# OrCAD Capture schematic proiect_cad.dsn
size Custom
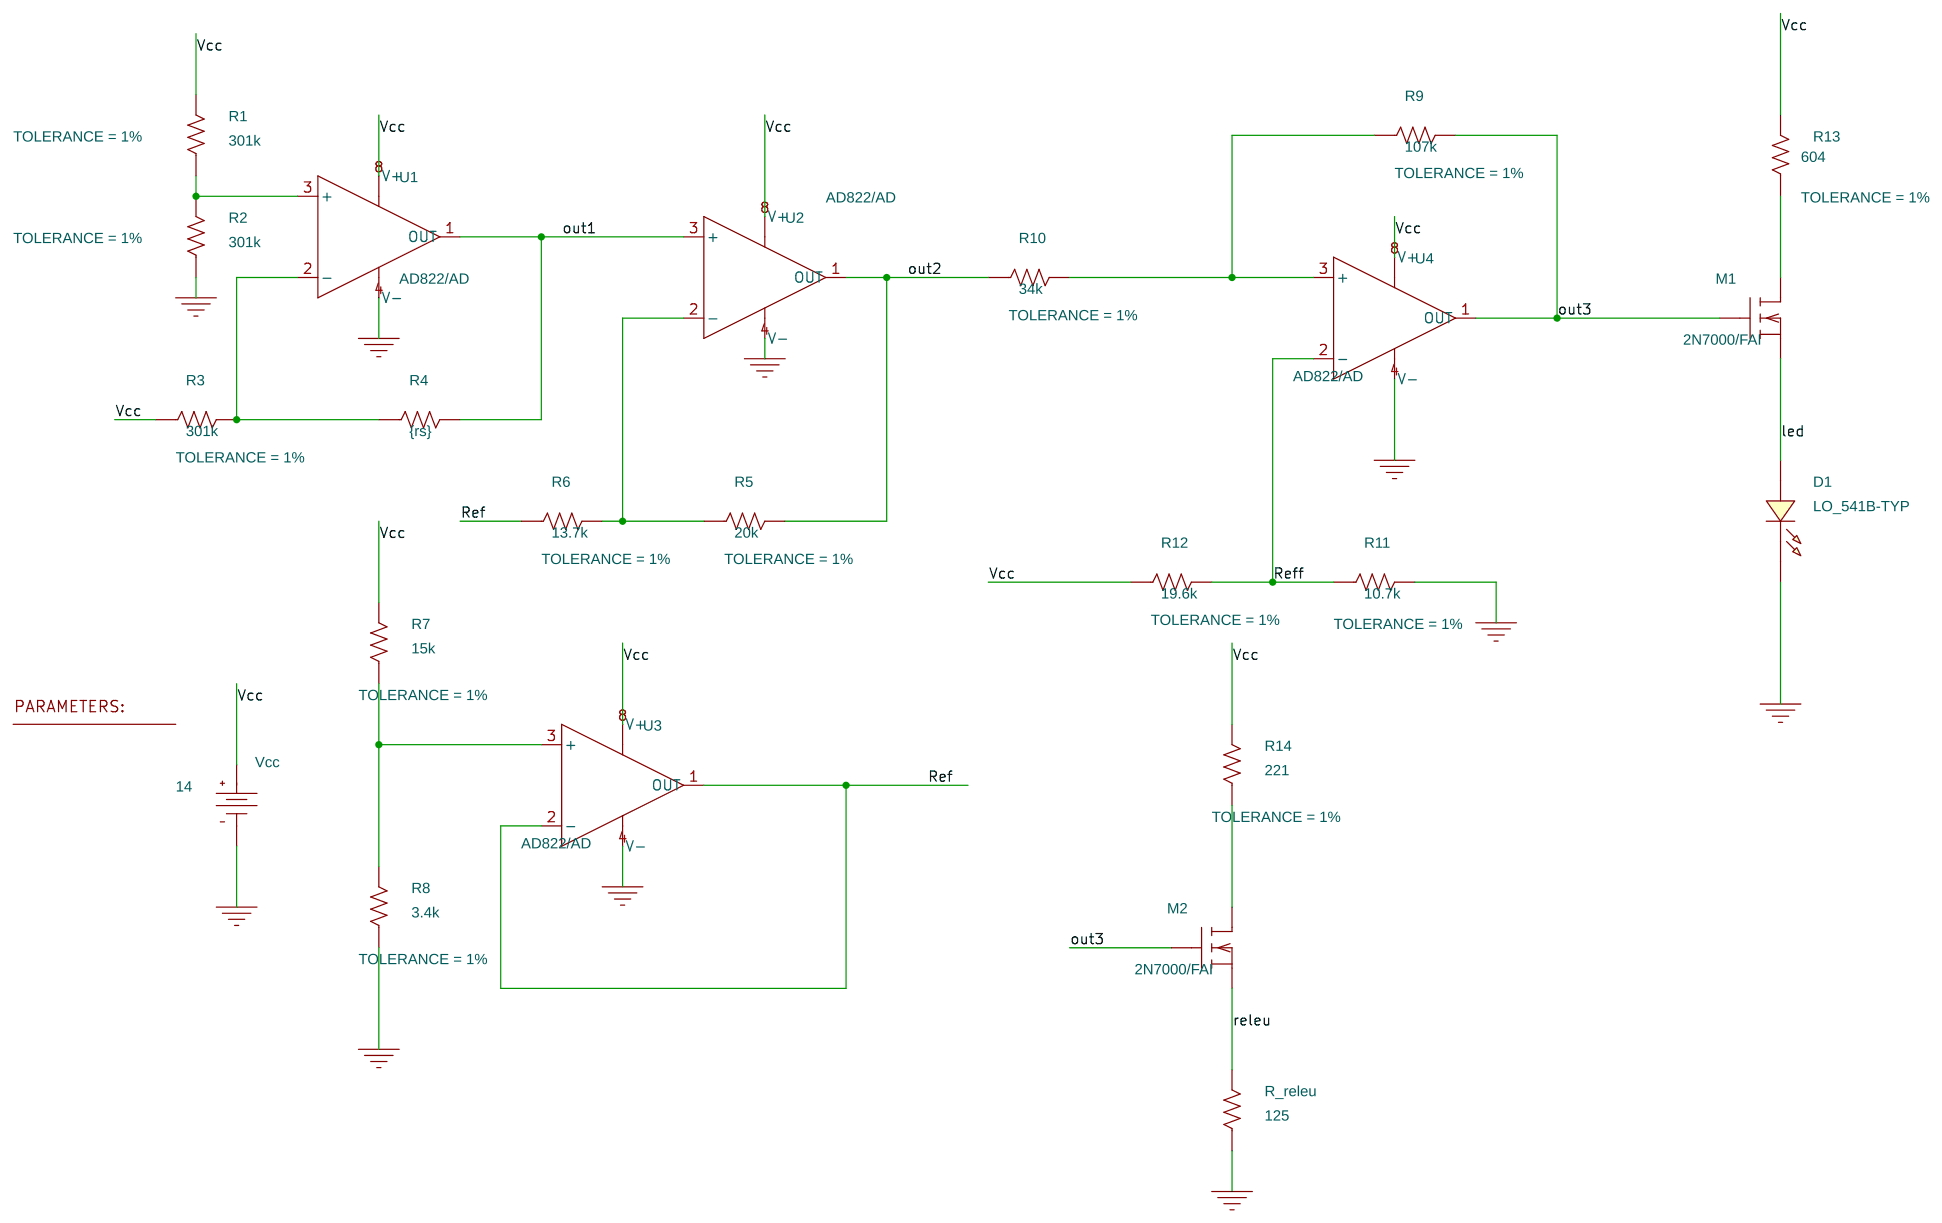
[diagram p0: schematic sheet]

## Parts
1  PARAM
D1  LO_541B-TYP
M1  2N7000/FAI  [TO92]
M2  2N7000/FAI  [TO92]
R1  301k  [AXRC05]
R2  301k  [AXRC05]
R3  301k  [AXRC05]
R4  {rs}  [AXRC05]
R5  20k  [AXRC05]
R6  13.7k  [AXRC05]
R7  15k  [AXRC05]
R8  3.4k  [AXRC05]
R9  107k  [AXRC05]
R10  34k  [AXRC05]
R11  10.7k  [AXRC05]
R12  19.6k  [AXRC05]
R13  604  [AXRC05]
R14  221  [AXRC05]
R_releu  125  [AXRC05]
U1  AD822/AD  [DIP1008W300L450]
U2  AD822/AD  [DIP1008W300L450]
U3  AD822/AD  [DIP1008W300L450]
U4  AD822/AD  [DIP1008W300L450]
Vcc  VDC

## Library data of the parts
1 = PARAM: releu: 1k; rled: 1k; rs: 100k
D1 = LO_541B-TYP
M1 M2 = 2N7000_FAI
R1-R3 R5-R14 = R: TOLERANCE: 1%
R4 R_releu = R
U1-U4 = AD822_AD
Vcc = VDC: DC: 14

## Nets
Vcc: R1.2 R3.1 R7.2 R12.1 R13.2 R14.2 U1.8(V+) U2.8(V+) U3.8(V+) U4.8(V+) Vcc.0(+)
0: D1.2 R2.1 R8.1 R11.2 R_releu.1 U1.4(V-) U2.4(V-) U3.4(V-) U4.4(V-) Vcc.1(-)
led: D1.1 M1.0(s)
out1: R4.2 U1.1(OUT) U2.3(+)
out2: R5.2 R10.1 U2.1(OUT)
out3: M1.1(g) M2.1(g) R9.2 U4.1(OUT)
Ref: R6.1 U3.1(OUT) U3.2(-)
Reff: R11.1 R12.2 U4.2(-)
releu: M2.0(s) R_releu.2
N00173: R1.1 R2.2 U1.3(+)
N00246: R3.2 R4.1 U1.2(-)
N00681: R5.1 R6.2 U2.2(-)
N00855: R7.1 R8.2 U3.3(+)
N01220: R9.1 R10.2 U4.3(+)
N01752: M1.2(d) R13.1
N01997: M2.2(d) R14.1
